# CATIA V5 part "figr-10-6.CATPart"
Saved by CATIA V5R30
Part number: Part1
Bounding box of the stored display mesh (mm): x -9.888 to 10, y -9.972 to 9.972, z 0 to 10
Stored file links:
  D:\PROJECTS\CATIA V56R 2020\Resources\Parts File\c10_catia_v5_6r2020_prt\figr-10-6.CATPart
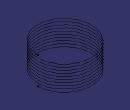
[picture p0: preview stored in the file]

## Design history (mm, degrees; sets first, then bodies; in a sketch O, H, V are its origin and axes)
Set1
  Helix1: Direction {line stored without definition}, RefPoint {point type Coord, X 10, Y 0, Z 0}, Pitch 1, Height 10, TaperAngle 0
Body1 (main body)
